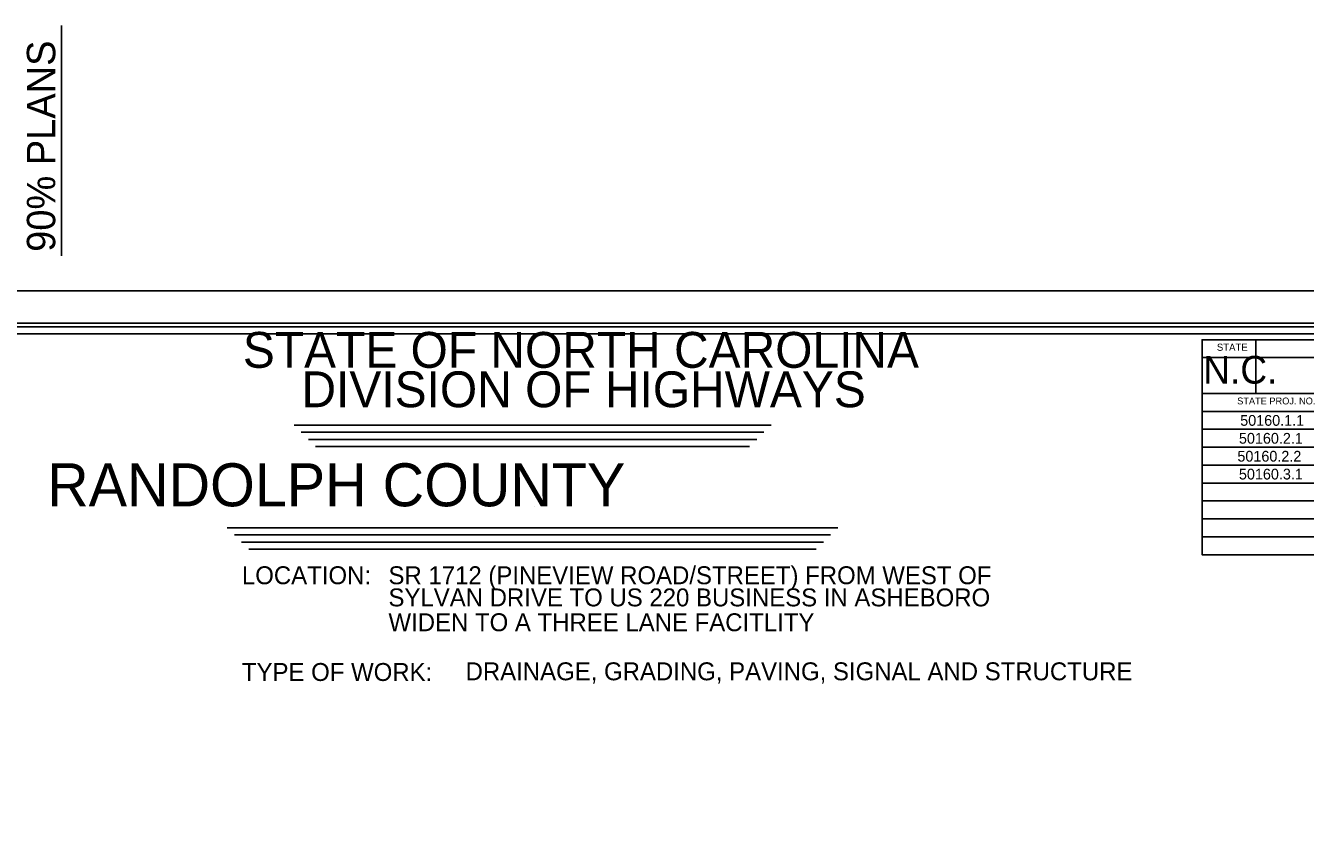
# Model space of a CAD drawing. Extents: x 1750553 to 1763838, y 734059 to 742526.
# Drawn here: x 1755472 to 1760830, y 738852 to 742272 of the extents above; entities that cross this region are included whole.
import ezdxf

# ---------------------------------------------------------------- set-up
doc = ezdxf.new("R2010")
doc.units = 0
for name, color, linetype in [('Old_Level_1', 7, 'Continuous'), ('Scratch_Level_3', 7, 'Continuous'), ('Sheet Cutting Line CELL', 7, 'Continuous'), ('Sheet Plot Border Inside CELL', 7, 'Continuous'), ('Sheet Plot Border Outside CELL', 7, 'Continuous'), ('Sheet Title CELL', 7, 'Continuous'), ('Sheet Title Data Points CELL', 7, 'Continuous')]:
    doc.layers.add(name, color=color, linetype=linetype)

msp = doc.modelspace()

# ---------------------------------------------------------------- linework, layer by layer
at = {"layer": 'Old_Level_1'}
msp.add_line((1755622.3, 741308.4), (1755622.3, 742271.9), dxfattribs=at)
at = {"layer": 'Sheet Cutting Line CELL'}
msp.add_line((1752099.6, 741160.9), (1762203.6, 741160.9), dxfattribs=at)
at = {"layer": 'Sheet Plot Border Inside CELL'}
msp.add_lwpolyline([(1752177.6, 734695.6), (1762176.6, 734695.6), (1762176.6, 741026.2), (1752177.6, 741026.2)], close=True, dxfattribs=at)
at = {"layer": 'Sheet Plot Border Outside CELL'}
msp.add_lwpolyline([(1762203.6, 741160.9), (1752099.6, 741160.9), (1752099.6, 734560.9), (1762203.6, 734560.9)], close=True, dxfattribs=at)
at = {"layer": 'Sheet Title CELL'}
for p, q in [((1756596, 740599.6), (1758592.5, 740599.6)), ((1756626, 740569.6), (1758562.5, 740569.6)), ((1756656, 740539.6), (1758532.5, 740539.6)), ((1756686, 740509.6), (1758502.5, 740509.6)), ((1756316.1, 740170), (1758872.1, 740170)), ((1756346.1, 740140), (1758842.1, 740140)), ((1756376.1, 740110), (1758812.1, 740110)), ((1756406.1, 740080), (1758782.1, 740080))]:
    msp.add_line(p, q, dxfattribs=at)
for points in [[(1762041.7, 741010.9), (1753161.5, 741010.9)], [(1762011.6, 740980.9), (1753491.7, 740980.9)], [(1762047.6, 740956.9), (1760397.6, 740956.9), (1760397.6, 740056.9), (1760947.5, 740056.9)], [(1760947.5, 740731.9), (1760622.6, 740731.9), (1760622.6, 740956.9), (1761597.7, 740956.9)], [(1762047.6, 740731.9), (1760397.6, 740731.9), (1760397.6, 740881.9), (1762047.6, 740881.9)], [(1762047.6, 740581.9), (1760397.6, 740581.9), (1760397.6, 740656.9), (1762047.6, 740656.9)], [(1762047.6, 740431.9), (1760397.6, 740431.9), (1760397.6, 740506.9), (1762047.6, 740506.9)], [(1762047.6, 740281.9), (1760397.7, 740281.9), (1760397.6, 740356.9), (1762047.6, 740356.9)], [(1762047.6, 740131.9), (1760397.6, 740131.9), (1760397.6, 740206.9), (1762047.6, 740206.9)], [(1760397.6, 740056.9), (1762047.6, 740056.9)]]:
    msp.add_lwpolyline(points, dxfattribs=at)
at = {"layer": 'Sheet Title Data Points CELL'}
for p, q in [((1757603.4, 740259.4), (1757603.4, 740259.4)), ((1758323.7, 739933.3), (1758323.7, 739933.3))]:
    msp.add_line(p, q, dxfattribs=at)

# ---------------------------------------------------------------- texts
at = {"layer": 'Old_Level_1'}
msp.add_text('90% PLANS', height=119, rotation=89.9975, dxfattribs=at).set_placement((1755595.8, 741324.8))
at = {"layer": 'Scratch_Level_3'}
for s, height, p in [('50160.1.1', 45, (1760556.9, 740596.6)), ('       RANDOLPH COUNTY       ', 180, (1755093.8, 740259.4)), ('50160.3.1', 45, (1760551.5, 740371.7)), ('SR 1712 (PINEVIEW ROAD/STREET) FROM WEST OF ', 75.001, (1756990.9, 739933.3)), ('SYLVAN DRIVE TO US 220 BUSINESS IN ASHEBORO', 75.001, (1756990.9, 739840.5)), ('WIDEN TO A THREE LANE FACITLITY', 75.001, (1756990.9, 739736.5)), ('DRAINAGE, GRADING, PAVING, SIGNAL AND STRUCTURE', 75.001, (1757313.7, 739531.1))]:
    msp.add_text(s, height=height, dxfattribs=at).set_placement(p)
for s, p in [('50160.2.1', (1760551.5, 740521.6)), ('50160.2.2', (1760545.1, 740446.6))]:
    msp.add_text(s, height=45, rotation=360, dxfattribs=at).set_placement(p)
at = {"layer": 'Sheet Title CELL'}
for s, height, p in [('STATE OF NORTH CAROLINA', 149.999, (1756381.2, 740839.3)), ('STATE', 30, (1760459.1, 740910.4)), ('N.C.', 116.1, (1760402.1, 740773)), ('DIVISION OF HIGHWAYS', 149.999, (1756626.6, 740674.3)), ('STATE PROJ. NO.', 28.8, (1760544.3, 740686)), ('LOCATION: ', 75, (1756377.3, 739933.3)), ('TYPE OF WORK:', 75.001, (1756377.3, 739528.3))]:
    msp.add_text(s, height=height, rotation=360, dxfattribs=at).set_placement(p)

doc.saveas('drawing.dxf')
